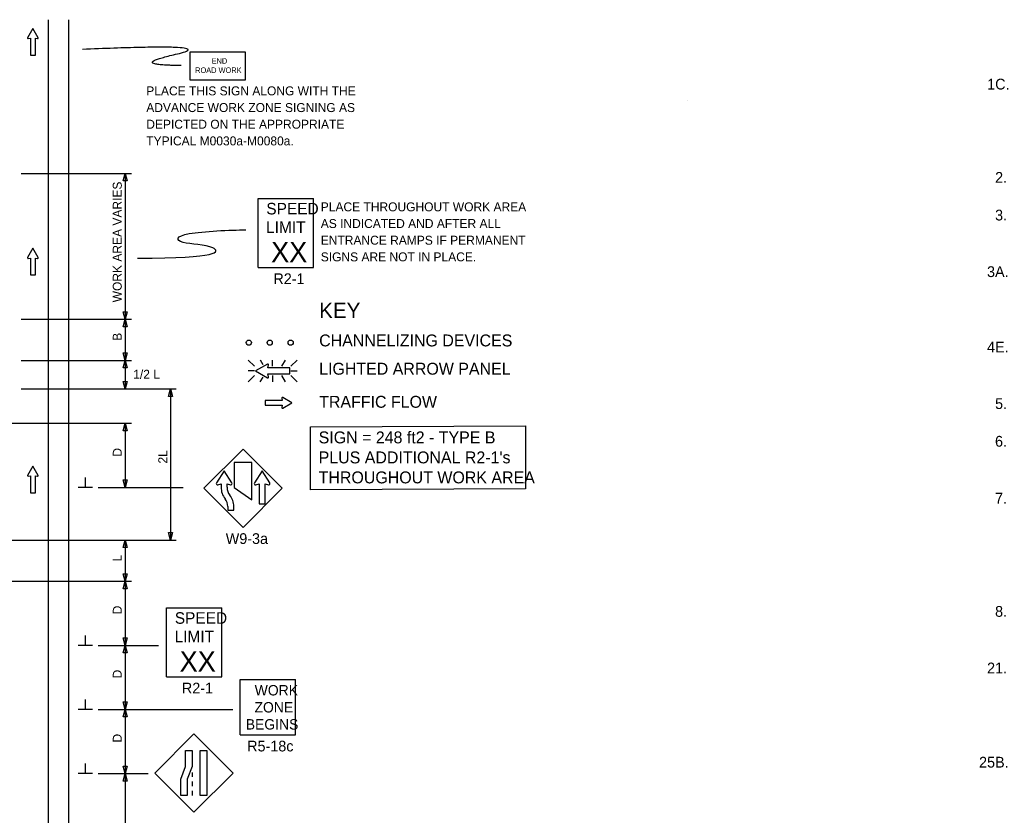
# Model space of a CAD drawing. Extents: x 16595 to 19519, y 6994 to 8256.
# Drawn here: x 17022 to 17793, y 7592 to 8212 of the extents above; entities that cross this region are included whole.
import ezdxf

# ---------------------------------------------------------------- set-up
doc = ezdxf.new("R2010")
doc.units = 0
for name, color, linetype in [('MT_SCRATCH_LEVEL_E', 7, 'Continuous'), ('PAVT_EDGE_EX', 7, 'Continuous'), ('TRAFFIC_SIGNS_PR', 7, 'Continuous'), ('TYPICAL_TEXT_DIMEN_EX', 7, 'Continuous'), ('TYPICAL_TEXT_DIMEN_PR', 7, 'Continuous')]:
    doc.layers.add(name, color=color, linetype=linetype)

msp = doc.modelspace()

# ---------------------------------------------------------------- linework, layer by layer
at = {"layer": 'MT_SCRATCH_LEVEL_E'}
for p, q in [((17032.13, 8205.38), (17028.01, 8198.14)), ((17036.27, 8198.14), (17032.13, 8205.38)), ((17028.5, 8197.45), (17030.27, 8197.77)), ((17030.27, 8197.77), (17030.27, 8184.51)), ((17034.02, 8184.51), (17034.02, 8197.77)), ((17034.02, 8197.77), (17035.79, 8197.45)), ((17030.27, 8184.51), (17034.02, 8184.51)), ((17032.13, 8033.96), (17028.01, 8026.72)), ((17036.27, 8026.72), (17032.13, 8033.96)), ((17028.5, 8026.04), (17030.27, 8026.35)), ((17030.27, 8026.35), (17030.27, 8013.1)), ((17034.02, 8013.1), (17034.02, 8026.35)), ((17034.02, 8026.35), (17035.79, 8026.04)), ((17030.27, 8013.1), (17034.02, 8013.1)), ((17226.19, 7917.05), (17226.5, 7915.27)), ((17226.19, 7917.05), (17226.5, 7915.27)), ((17234.11, 7913.42), (17226.87, 7917.53)), ((17234.11, 7913.42), (17226.87, 7917.53)), ((17226.5, 7915.27), (17213.24, 7915.27)), ((17213.24, 7915.27), (17213.24, 7911.53)), ((17226.5, 7915.27), (17213.24, 7915.27)), ((17213.24, 7915.27), (17213.24, 7911.53)), ((17213.24, 7911.53), (17226.5, 7911.53)), ((17213.24, 7911.53), (17226.5, 7911.53)), ((17226.5, 7911.53), (17226.19, 7909.75)), ((17226.5, 7911.53), (17226.19, 7909.75)), ((17226.87, 7909.27), (17234.11, 7913.42)), ((17226.87, 7909.27), (17234.11, 7913.42)), ((17032.13, 7864.11), (17028.01, 7856.86)), ((17036.27, 7856.86), (17032.13, 7864.11)), ((17028.5, 7856.18), (17030.27, 7856.5)), ((17030.27, 7856.5), (17030.27, 7843.24)), ((17034.02, 7843.24), (17034.02, 7856.5)), ((17034.02, 7856.5), (17035.79, 7856.18)), ((17030.27, 7843.24), (17034.02, 7843.24))]:
    msp.add_line(p, q, dxfattribs=at)
for centre, start, end in [((17028.42, 8197.91), 150.42484, 279.96381), ((17035.86, 8197.91), 260.03619, 29.77312), ((17028.42, 8026.5), 150.42484, 279.96381), ((17035.86, 8026.5), 260.03619, 29.77312), ((17226.65, 7917.12), 60.42484, 189.96381), ((17226.65, 7917.12), 60.42484, 189.96381), ((17226.65, 7909.68), 170.03619, 299.77312), ((17226.65, 7909.68), 170.03619, 299.77312), ((17028.42, 7856.64), 150.42484, 279.96381), ((17035.86, 7856.64), 260.03619, 29.77312)]:
    msp.add_arc(centre, 0.463, start, end, dxfattribs=at)
at = {"layer": 'PAVT_EDGE_EX'}
for p, q in [((17043.95, 8212.14), (17043.95, 7351.67)), ((17059.95, 8212.14), (17059.95, 7351.67))]:
    msp.add_line(p, q, dxfattribs=at)
at = {"layer": 'TRAFFIC_SIGNS_PR'}
for p, q in [((17207.63, 8072.87), (17250.83, 8072.87)), ((17207.63, 8018.87), (17207.63, 8072.87)), ((17250.83, 8018.87), (17250.83, 8072.87)), ((17207.63, 8018.87), (17250.83, 8018.87)), ((17199.92, 7946.8), (17204.85, 7941.87)), ((17211.68, 7942.98), (17209.48, 7946.8)), ((17219, 7941.87), (17219, 7946.8)), ((17226.24, 7941.87), (17229.09, 7946.8)), ((17233.15, 7941.87), (17238.09, 7946.8)), ((17204.85, 7938.31), (17199.92, 7938.31)), ((17199.92, 7929.82), (17204.85, 7934.76)), ((17209.43, 7929.82), (17211.55, 7933.48)), ((17219, 7934.76), (17219, 7929.82)), ((17229.13, 7929.82), (17226.28, 7934.76)), ((17233.15, 7938.31), (17238.09, 7938.31)), ((17233.15, 7934.76), (17238.09, 7929.82)), ((17196.04, 7877.31), (17165.49, 7846.76)), ((17226.59, 7846.76), (17196.04, 7877.31)), ((17165.49, 7846.76), (17196.04, 7816.22)), ((17196.04, 7816.22), (17226.59, 7846.76)), ((17136.28, 7753.64), (17179.48, 7753.64)), ((17136.28, 7699.64), (17136.28, 7753.64)), ((17179.48, 7699.64), (17179.48, 7753.64)), ((17136.28, 7699.64), (17179.48, 7699.64)), ((17193.79, 7654.41), (17193.79, 7697.61)), ((17193.79, 7697.61), (17236.99, 7697.61)), ((17236.99, 7654.41), (17236.99, 7697.61)), ((17157.66, 7655.24), (17127.11, 7624.69)), ((17188.21, 7624.69), (17157.66, 7655.24)), ((17193.79, 7654.41), (17236.99, 7654.41)), ((17127.11, 7624.69), (17157.66, 7594.14)), ((17156.26, 7625.24), (17156.26, 7621.64)), ((17157.66, 7594.14), (17188.21, 7624.69)), ((17156.26, 7618.04), (17156.26, 7614.44)), ((17156.26, 7610.84), (17156.26, 7607.24))]:
    msp.add_line(p, q, dxfattribs=at)
for points in [[(17154.58, 8165.32), (17197.78, 8165.32), (17197.78, 8186.93), (17154.58, 8186.93)], [(17188.94, 7866.93), (17188.94, 7847.42), (17202.9, 7837.72), (17202.9, 7866.93)], [(17156.26, 7642.4), (17156.26, 7629.82), (17152.5, 7619.82), (17152.5, 7607.24), (17147.44, 7607.24), (17147.44, 7619.82), (17151.2, 7629.82), (17151.2, 7642.4)], [(17167.66, 7642.4), (17167.66, 7607.24), (17162.61, 7607.24), (17162.61, 7642.4)]]:
    msp.add_lwpolyline(points, close=True, dxfattribs=at)
for points in [[(17214.93, 7943.59), (17205.64, 7938.31), (17214.93, 7932.99)], [(17215.81, 7933.62), (17215.41, 7935.89), (17232.42, 7935.89), (17232.42, 7940.69), (17215.41, 7940.69), (17215.81, 7942.97)], [(17187.26, 7850.93), (17181.26, 7860.34), (17175.27, 7850.93)], [(17216.76, 7850.93), (17210.77, 7860.34), (17204.78, 7850.93)], [(17176.32, 7849.51), (17178.9, 7850.22), (17178.9, 7847.71)], [(17183.62, 7847.59), (17183.62, 7850.22), (17186.21, 7849.51)], [(17205.83, 7849.51), (17208.41, 7850.22), (17208.41, 7834.69), (17213.13, 7834.69), (17213.13, 7850.22), (17215.72, 7849.51)], [(17184.04, 7832.58), (17184.03, 7829.59), (17188.76, 7829.59), (17188.76, 7832.58)]]:
    msp.add_lwpolyline(points, dxfattribs=at)
for centre in [(17200.48, 7960.34), (17216.78, 7960.34), (17233.08, 7960.34)]:
    msp.add_circle(centre, 2, dxfattribs=at)
for centre, radius, start, end in [((17215.22, 7943.06), 0.598, 350.73078, 118.89165), ((17215.22, 7933.51), 0.597, 241.48329, 9.95933), ((17176.07, 7850.42), 0.945, 147.52044, 285.3986), ((17193.06, 7847.29), 14.17, 178.32933, 218.54273), ((17193.06, 7847.29), 9.45, 178.19356, 218.54646), ((17171.81, 7847.97), 11.81, 358.18937, 0.00483), ((17186.46, 7850.42), 0.947, 254.68281, 32.2708), ((17183.09, 7838.12), 11.81, 74.67996, 74.68078), ((17197.22, 7857.27), 11.81, 212.45689, 212.46649), ((17205.58, 7850.42), 0.946, 147.54971, 285.33159), ((17215.97, 7850.42), 0.943, 254.67777, 32.46648), ((17226.73, 7857.27), 11.81, 212.45689, 212.46649), ((17174.58, 7832.57), 14.17, 0, 38.5422), ((17174.58, 7832.57), 9.45, 0, 38.54567)]:
    msp.add_arc(centre, radius, start, end, dxfattribs=at)
msp.add_open_spline([(17147.61, 8176.5), (17105.1, 8176.5), (17181.62, 8193.91), (17070.83, 8188.97)], degree=2, dxfattribs=at)
at = {"layer": 'TYPICAL_TEXT_DIMEN_EX'}
msp.add_lwpolyline([(17248.63, 7894.77), (17416.3, 7895.51), (17416.3, 7846.4), (17248.63, 7845.65)], close=True, dxfattribs=at)
at = {"layer": 'TYPICAL_TEXT_DIMEN_PR'}
for p, q in [((17022.89, 8092.31), (17108.95, 8092.31)), ((17102.38, 8086.45), (17103.95, 8092.31)), ((17103.95, 8086.45), (17102.38, 8086.45)), ((17103.95, 8092.31), (17103.95, 7978.58)), ((17103.95, 8092.31), (17105.52, 8086.45)), ((17105.52, 8086.45), (17103.95, 8086.45)), ((17022.89, 7978.58), (17108.95, 7978.58)), ((17103.95, 7978.58), (17102.38, 7984.44)), ((17102.38, 7984.44), (17103.95, 7984.44)), ((17102.38, 7972.72), (17103.95, 7978.58)), ((17103.95, 7984.44), (17105.52, 7984.44)), ((17105.52, 7984.44), (17103.95, 7978.58)), ((17103.95, 7978.58), (17103.95, 7946.51)), ((17103.95, 7978.58), (17105.52, 7972.72)), ((17103.95, 7972.72), (17102.38, 7972.72)), ((17105.52, 7972.72), (17103.95, 7972.72)), ((17103.95, 7946.51), (17102.38, 7952.37)), ((17102.38, 7952.37), (17103.95, 7952.37)), ((17103.95, 7953.6), (17103.95, 7950)), ((17103.95, 7952.37), (17105.52, 7952.37)), ((17105.52, 7952.37), (17103.95, 7946.51)), ((17022.89, 7946.51), (17108.95, 7946.51)), ((17102.38, 7940.64), (17103.95, 7946.51)), ((17103.95, 7940.64), (17102.38, 7940.64)), ((17103.95, 7946.51), (17103.95, 7924.26)), ((17103.95, 7946.51), (17105.52, 7940.64)), ((17105.52, 7940.64), (17103.95, 7940.64)), ((17022.89, 7924.26), (17143.76, 7924.26)), ((17103.95, 7924.26), (17102.38, 7930.12)), ((17102.38, 7930.12), (17103.95, 7930.12)), ((17103.95, 7930.12), (17105.52, 7930.12)), ((17105.52, 7930.12), (17103.95, 7924.26)), ((17137.86, 7918.4), (17139.43, 7924.26)), ((17139.43, 7924.26), (17139.43, 7806.38)), ((17139.43, 7924.26), (17141, 7918.4)), ((17139.43, 7918.4), (17137.86, 7918.4)), ((17141, 7918.4), (17139.43, 7918.4)), ((17000.85, 7897.45), (17108.95, 7897.45)), ((17102.38, 7891.59), (17103.95, 7897.45)), ((17103.95, 7897.45), (17103.95, 7847.45)), ((17103.95, 7897.45), (17105.52, 7891.59)), ((17103.95, 7891.59), (17102.38, 7891.59)), ((17105.52, 7891.59), (17103.95, 7891.59)), ((17073.07, 7847.45), (17073.07, 7855.24)), ((17078.7, 7847.45), (17067.45, 7847.45)), ((17082.95, 7847.45), (17149.18, 7847.45)), ((17103.95, 7847.45), (17102.38, 7853.31)), ((17102.38, 7853.31), (17103.95, 7853.31)), ((17103.95, 7853.31), (17105.52, 7853.31)), ((17105.52, 7853.31), (17103.95, 7847.45)), ((17143.8, 7847.45), (17147.6, 7847.45)), ((17139.43, 7806.38), (17137.86, 7812.24)), ((17137.86, 7812.24), (17139.43, 7812.24)), ((17139.43, 7812.24), (17141, 7812.24)), ((17141, 7812.24), (17139.43, 7806.38)), ((16999.7, 7806.38), (17143.76, 7806.38)), ((17102.38, 7800.52), (17103.95, 7806.38)), ((17103.95, 7800.52), (17102.38, 7800.52)), ((17103.95, 7806.38), (17103.95, 7774.28)), ((17103.95, 7806.38), (17105.52, 7800.52)), ((17105.52, 7800.52), (17103.95, 7800.52)), ((17103.95, 7774.28), (17102.38, 7780.14)), ((17102.38, 7780.14), (17103.95, 7780.14)), ((17103.95, 7780.14), (17105.52, 7780.14)), ((17105.52, 7780.14), (17103.95, 7774.28)), ((16980.35, 7774.28), (17108.95, 7774.28)), ((17102.38, 7768.42), (17103.95, 7774.28)), ((17103.95, 7774.28), (17103.95, 7724.28)), ((17103.95, 7774.28), (17105.52, 7768.42)), ((17103.95, 7768.42), (17102.38, 7768.42)), ((17105.52, 7768.42), (17103.95, 7768.42)), ((17073.07, 7724.28), (17073.07, 7732.06)), ((17078.7, 7724.28), (17067.45, 7724.28)), ((17082.95, 7724.28), (17130.07, 7724.28)), ((17103.95, 7724.28), (17102.38, 7730.14)), ((17102.38, 7730.14), (17103.95, 7730.14)), ((17102.38, 7718.42), (17103.95, 7724.28)), ((17103.95, 7730.14), (17105.52, 7730.14)), ((17105.52, 7730.14), (17103.95, 7724.28)), ((17103.95, 7724.28), (17105.52, 7718.42)), ((17103.95, 7724.28), (17103.95, 7674.28)), ((17103.95, 7718.42), (17102.38, 7718.42)), ((17105.52, 7718.42), (17103.95, 7718.42)), ((17073.07, 7674.28), (17073.07, 7682.06)), ((17103.95, 7674.28), (17102.38, 7680.14)), ((17102.38, 7680.14), (17103.95, 7680.14)), ((17103.95, 7680.14), (17105.52, 7680.14)), ((17105.52, 7680.14), (17103.95, 7674.28)), ((17078.7, 7674.28), (17067.45, 7674.28)), ((17082.95, 7674.28), (17187.91, 7674.28)), ((17102.38, 7668.42), (17103.95, 7674.28)), ((17103.95, 7674.28), (17105.52, 7668.42)), ((17103.95, 7674.28), (17103.95, 7624.28)), ((17103.95, 7668.42), (17102.38, 7668.42)), ((17105.52, 7668.42), (17103.95, 7668.42)), ((17073.07, 7624.28), (17073.07, 7632.06)), ((17078.7, 7624.28), (17067.45, 7624.28)), ((17082.95, 7624.28), (17121.95, 7624.28)), ((17103.95, 7624.28), (17102.38, 7630.14)), ((17102.38, 7630.14), (17103.95, 7630.14)), ((17102.38, 7618.42), (17103.95, 7624.28)), ((17103.95, 7630.14), (17105.52, 7630.14)), ((17105.52, 7630.14), (17103.95, 7624.28)), ((17103.95, 7624.28), (17103.95, 7524.28)), ((17103.95, 7624.28), (17105.52, 7618.42)), ((17103.95, 7618.42), (17102.38, 7618.42)), ((17105.52, 7618.42), (17103.95, 7618.42))]:
    msp.add_line(p, q, dxfattribs=at)
for points, degree in [([(17542.61, 8148.9), (17542.62, 8148.9), (17542.63, 8148.9), (17542.63, 8148.9)], 2), ([(17270.25, 8131.98), (17270.26, 8131.98), (17270.27, 8131.98), (17270.27, 8131.98)], 2), ([(17113.66, 8026.16), (17178.24, 8026.16), (17178.24, 8036.91), (17143.33, 8036.91), (17143.33, 8046.58), (17186.19, 8048.1), (17198.1, 8048.36)], 3), ([(17223.23, 8033.57), (17223.25, 8033.57), (17223.26, 8033.57), (17223.26, 8033.57)], 2)]:
    msp.add_open_spline(points, degree=degree, dxfattribs=at)

# ---------------------------------------------------------------- texts
at = {"layer": 'TRAFFIC_SIGNS_PR'}
for s, height, p in [('END', 4.31, (17171.46, 8177.85)), ('ROAD WORK', 4.31, (17158.64, 8170.66)), ('PLACE THIS SIGN ALONG WITH THE', 7, (17120.51, 8153.17)), ('ADVANCE WORK ZONE SIGNING AS', 7, (17120.51, 8140.17)), ('DEPICTED ON THE APPROPRIATE', 7, (17120.51, 8127.17)), ('TYPICAL M0030a-M0080a.', 7, (17120.51, 8114.17)), ('SPEED', 9, (17214.12, 8060.34)), ('PLACE THROUGHOUT WORK AREA', 7, (17256.58, 8062.73)), ('LIMIT', 9, (17213.94, 8045.94)), ('AS INDICATED AND AFTER ALL', 7, (17256.58, 8049.73)), ('ENTRANCE RAMPS IF PERMANENT', 7, (17256.58, 8036.73)), ('XX', 15.785, (17217.88, 8023.1)), ('SIGNS ARE NOT IN PLACE.', 7, (17256.58, 8023.73)), ('R2-1', 8.37, (17219.64, 8006)), ('W9-3a', 8.37, (17182.47, 7803.35)), ('SPEED', 9, (17142.76, 7741.11)), ('LIMIT', 9, (17142.58, 7726.71)), ('XX', 15.785, (17146.53, 7703.87)), ('R2-1', 8.37, (17148.29, 7686.77)), ('WORK', 8.119, (17205.04, 7685.2)), ('ZONE', 8.119, (17204.91, 7671.91)), ('BEGINS', 8.119, (17198.08, 7658.62)), ('R5-18c', 8.37, (17199.2, 7641.54))]:
    msp.add_text(s, height=height, dxfattribs=at).set_placement(p)
at = {"layer": 'TYPICAL_TEXT_DIMEN_EX'}
for s, height, p in [('KEY', 12, (17255.33, 7979.45)), ('CHANNELIZING DEVICES', 9.3, (17255.33, 7957.4)), ('LIGHTED ARROW PANEL', 9.3, (17255.33, 7935.35)), ('TRAFFIC FLOW', 9.3, (17255.33, 7909.55)), ('SIGN = 248 ft2 - TYPE B', 9.3, (17254.92, 7881.79)), ("PLUS ADDITIONAL R2-1's", 9.3, (17254.92, 7866.19)), ('THROUGHOUT WORK AREA', 9.3, (17254.92, 7850.59))]:
    msp.add_text(s, height=height, dxfattribs=at).set_placement(p)
at = {"layer": 'TYPICAL_TEXT_DIMEN_PR'}
for s, height, p in [('1C.', 8.4, (17776.19, 8157.75)), ('2.', 8.4, (17782.39, 8085)), ('3.', 8.4, (17782.39, 8055.6)), ('3A.', 8.4, (17776.09, 8011.49)), ('4E.', 8.4, (17776.13, 7952.7)), ('1/2 L', 7, (17110.35, 7932.18)), ('5.', 8.4, (17782.39, 7908.6)), ('6.', 8.4, (17782.34, 7879.2)), ('7.', 8.4, (17782.34, 7834.84)), ('8.', 8.4, (17782.39, 7746.54)), ('21.', 8.4, (17776.14, 7702.44)), ('25B.', 8.4, (17769.88, 7628.94))]:
    msp.add_text(s, height=height, dxfattribs=at).set_placement(p)
for s, p in [('WORK AREA VARIES', (17101.39, 7991.8)), ('B', (17101.39, 7961.78)), ('D', (17101.39, 7871.43)), ('2L', (17136.87, 7866.04)), ('L', (17101.39, 7789.69)), ('D', (17101.39, 7748.5)), ('D', (17101.39, 7698.5)), ('D', (17101.39, 7648.5))]:
    msp.add_text(s, height=7, rotation=90, dxfattribs=at).set_placement(p)

doc.saveas('drawing.dxf')
